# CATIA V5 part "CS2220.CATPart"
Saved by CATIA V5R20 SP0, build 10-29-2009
Part number: CS2220
Revision: 4
Definition: design
Nomenclature: CS2220
Source: made
Description: NOT SPECIFIED
Bounding box of the stored display mesh (mm): x -18.807 to 19, y -19 to 19, z -36 to 9
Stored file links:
  C:\Users\Raffaele\Desktop\3D X SITO CF\BOLEX\20-TILTED COLUMN SUPPORT\CS2220.CATPart
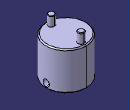
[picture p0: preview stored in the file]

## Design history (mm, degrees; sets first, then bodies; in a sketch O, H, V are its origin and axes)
Body1 "MANIFOLD_SOLID_BREP #695" (main body)
  Solid1: solid without history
